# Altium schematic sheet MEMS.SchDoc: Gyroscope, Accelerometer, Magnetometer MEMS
size A4; Date: 01-DEC-2013; Author: A.B; CompanyName: STMicroelectronics; Organization: Microcontrollers Division; Address1: 12, Rue Jules HOROWITZ; Address2: 38019 Grenoble; Address3: FRANCE; DocumentNumber: MB1184; Revision: C-01; SheetNumber: 10; SheetTotal: 10; Project: STM32L476G-DISCO
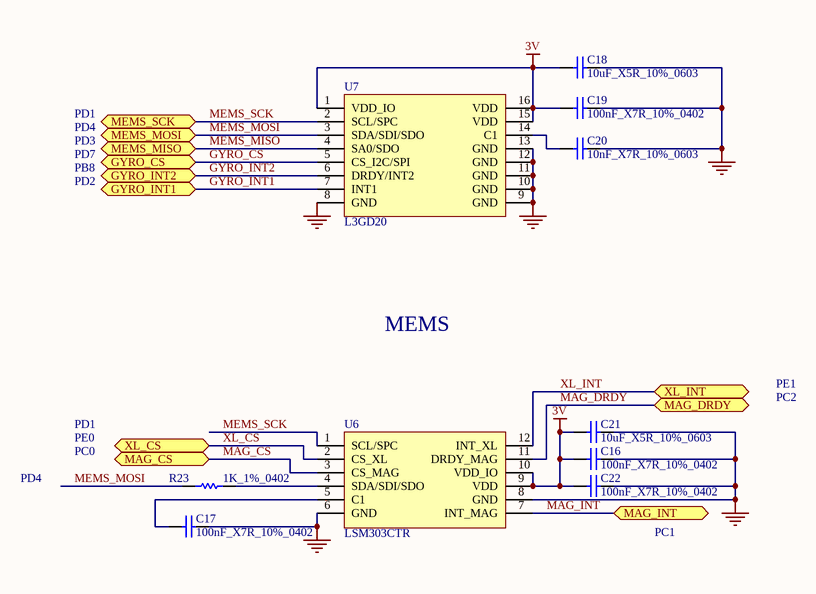
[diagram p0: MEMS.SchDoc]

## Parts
C16  100nF_X7R_10%_0402  [0402C]
C17  100nF_X7R_10%_0402  [0402C]
C18  10uF_X5R_10%_0603  [0603C]
C19  100nF_X7R_10%_0402  [0402C]
C20  10nF_X7R_10%_0603  [0603C]
C21  10uF_X5R_10%_0603  [0603C]
C22  100nF_X7R_10%_0402  [0402C]
R23  1K_1%_0402  [0402R]
U6  LSM303CTR  [LGA12_2x2]
U7  L3GD20  [LGA16-4x4]

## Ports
GYRO_CS, GYRO_INT1, GYRO_INT2, MAG_CS, MAG_DRDY, MAG_INT, MEMS_MISO, MEMS_MOSI, MEMS_SCK, XL_CS, XL_INT

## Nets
3V: C16.1 C18.1 C19.1 C21.1 C22.1 U6.9(VDD) U6.10(VDD_IO) U7.1(VDD_IO) U7.15(VDD) U7.16(VDD)
GND: C16.2 C17.2 C18.2 C19.2 C20.2 C21.2 C22.2 U6.6(GND) U6.8(GND) U7.8(GND) U7.9(GND) U7.10(GND) U7.11(GND) U7.12(GND) U7.13(GND)
GYRO_CS: U7.5(CS_I2C/SPI) ; port GYRO_CS
GYRO_INT1: U7.7(INT1) ; port GYRO_INT1
GYRO_INT2: U7.6(DRDY/INT2) ; port GYRO_INT2
MAG_CS: U6.3(CS_MAG) ; port MAG_CS
MAG_DRDY: U6.11(DRDY_MAG) ; port MAG_DRDY
MAG_INT: U6.7(INT_MAG) ; port MAG_INT
MEMS_MISO: U7.4(SA0/SDO) ; port MEMS_MISO
MEMS_MOSI: R23.1 U7.3(SDA/SDI/SDO) ; port MEMS_MOSI
MEMS_SCK: U6.1(SCL/SPC) U7.2(SCL/SPC) ; port MEMS_SCK
XL_CS: U6.2(CS_XL) ; port XL_CS
XL_INT: U6.12(INT_XL) ; port XL_INT
NetC17_1: C17.1 U6.5(C1)
NetC20_1: C20.1 U7.14(C1)
NetR23_2: R23.2 U6.4(SDA/SDI/SDO)

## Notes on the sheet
- PD7
- PD1
- PD3
- PD4
- PD2
- PB8
- MEMS
- PC2
- PE1
- PC0
- PE0
- PC1

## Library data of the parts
C16 C17 C19 C22 = Cap_100nF_X7R_10%_0402: Capacitor,100nF,16V,X7R,10%,0402,YAGEO; Manuf_Part_1: CC0402KRX7R7BB104
C18 C21 = Cap_10uF_X5R_10%_0603: Capacitor,10uF,6.3V,X5R,10%,0603,YAGEO; Manuf_Part_1: CC0603KRX5R5BB106
C20 = Cap_10nF_X7R_10%_0603: Capacitor,10nF,50V,X7R,10%,0603,YAGEO; Manuf_Part_1: CC0603KRX7R9BB103
R23 = Res_1K_1%_0402: Resistor,1K,0402,1%,YAGEO; Manuf_Part_1: RC0402FR-071KL
U6 = LSM303CTR: Ultra compact high performance e-compass 3D accelerometer and 3D magnetometer module; Manuf_1: STM; Provided: ST; Ref St: xxxxxxxx; ECCN_US/EU: EAR99/NEC
U7 = L3GD20: MEMS motion sensor three-axis digital output gyroscope, WHO_AM_I REGISTER --> AP3GDL20BCA="11010101", L3GD20="11010100"; Manuf_1: STM; Manuf_Part_1: L3GD20TR; Manuf_Part_2: AP3GDL20BC4; Provided: ST; Ref St: 9177042; ECCN_US/EU: EAR99/NEC; Ref St_2: 9177052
